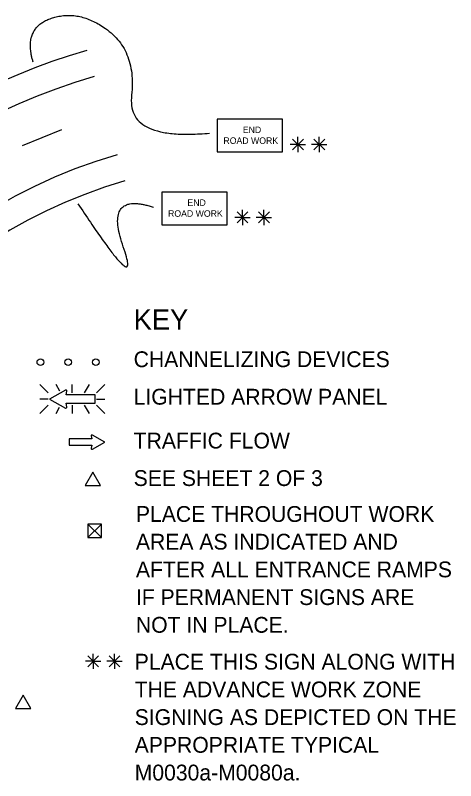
# Model space of a CAD drawing. Extents: x 16563 to 19504, y 6261 to 8279.
# Drawn here: x 17165.8 to 17424.8, y 7689.1 to 8139.2 of the extents above; entities that cross this region are included whole.
import ezdxf

# ---------------------------------------------------------------- set-up
doc = ezdxf.new("R2010")
doc.units = 0
for name, color, linetype in [('ALI_LEGAL_EX', 7, 'Continuous'), ('MT_SCRATCH_LEVEL_E', 7, 'Continuous'), ('PAVT_EDGE_EX', 7, 'Continuous'), ('TRAFFIC_SIGNS_PR', 7, 'Continuous'), ('TYPICAL_TEXT_DIMEN_EX', 7, 'Continuous'), ('TYPICAL_TEXT_DIMEN_PR', 7, 'Continuous')]:
    doc.layers.add(name, color=color, linetype=linetype)

msp = doc.modelspace()

# ---------------------------------------------------------------- linework, layer by layer
at = {"layer": 'ALI_LEGAL_EX'}
msp.add_lwpolyline([(17170.06, 8062.61), (17193.2, 8072.08)], dxfattribs=at)
at = {"layer": 'MT_SCRATCH_LEVEL_E'}
for p, q in [((17210.45, 7891.87), (17210.76, 7890.09)), ((17218.37, 7888.24), (17211.13, 7892.35)), ((17210.76, 7890.09), (17197.5, 7890.09)), ((17197.5, 7890.09), (17197.5, 7886.35)), ((17211.13, 7884.09), (17218.37, 7888.24)), ((17197.5, 7886.35), (17210.76, 7886.35)), ((17210.76, 7886.35), (17210.45, 7884.57))]:
    msp.add_line(p, q, dxfattribs=at)
for centre, start, end in [((17210.9, 7891.94), 60.4248, 189.9638), ((17210.9, 7884.5), 170.0362, 299.7731)]:
    msp.add_arc(centre, 0.463, start, end, dxfattribs=at)
at = {"layer": 'PAVT_EDGE_EX'}
for radius, end in [(380, 157.5011), (364, 165.0045), (316, 180), (300, 180)]:
    msp.add_arc((17314.02, 7753.78), radius, 106.2376, end, dxfattribs=at)
at = {"layer": 'TRAFFIC_SIGNS_PR'}
for p, q in [((17180.22, 7922.05), (17185.15, 7917.11)), ((17191.98, 7918.23), (17189.78, 7922.05)), ((17199.3, 7917.11), (17199.3, 7922.05)), ((17206.54, 7917.11), (17209.39, 7922.05)), ((17213.45, 7917.11), (17218.39, 7922.05)), ((17185.15, 7913.56), (17180.22, 7913.56)), ((17180.22, 7905.07), (17185.15, 7910)), ((17199.3, 7910), (17199.3, 7905.07)), ((17209.43, 7905.07), (17206.58, 7910)), ((17213.45, 7913.56), (17218.39, 7913.56)), ((17213.45, 7910), (17218.39, 7905.07)), ((17189.73, 7905.07), (17191.84, 7908.73))]:
    msp.add_line(p, q, dxfattribs=at)
for points in [[(17284.59, 8058.85), (17323, 8058.85), (17323, 8078.05), (17284.59, 8078.05)], [(17252.02, 8016), (17290.43, 8016), (17290.43, 8035.2), (17252.02, 8035.2)]]:
    msp.add_lwpolyline(points, close=True, dxfattribs=at)
for points in [[(17195.23, 7918.83), (17185.94, 7913.56), (17195.23, 7908.24)], [(17196.11, 7908.87), (17195.7, 7911.13), (17212.72, 7911.13), (17212.72, 7915.94), (17195.7, 7915.94), (17196.11, 7918.22)]]:
    msp.add_lwpolyline(points, dxfattribs=at)
for centre in [(17180.56, 7935.24), (17196.86, 7935.24), (17213.16, 7935.24)]:
    msp.add_circle(centre, 2, dxfattribs=at)
for centre, radius, start, end in [((17195.52, 7918.31), 0.598, 350.7308, 118.8916), ((17195.52, 7908.76), 0.597, 241.4833, 9.9593)]:
    msp.add_arc(centre, radius, start, end, dxfattribs=at)
at = {"layer": 'TYPICAL_TEXT_DIMEN_PR'}
for p, q in [((17332.02, 8063.22), (17332.02, 8067.68)), ((17344.58, 8063.22), (17344.58, 8067.68)), ((17332.02, 8063.22), (17327.49, 8063.22)), ((17328.83, 8066.41), (17335.21, 8060.03)), ((17335.21, 8066.41), (17328.83, 8060.03)), ((17332.02, 8063.22), (17335.21, 8063.22)), ((17332.02, 8063.22), (17336.5, 8063.22)), ((17332.02, 8063.22), (17332.02, 8058.72)), ((17344.58, 8063.22), (17340.04, 8063.22)), ((17341.39, 8066.41), (17347.76, 8060.03)), ((17347.76, 8066.41), (17341.39, 8060.03)), ((17344.58, 8063.22), (17347.76, 8063.22)), ((17344.58, 8063.22), (17349.06, 8063.22)), ((17344.58, 8063.22), (17344.58, 8058.72)), ((17296.26, 8023.56), (17302.64, 8017.18)), ((17302.64, 8023.56), (17296.26, 8017.18)), ((17299.45, 8020.37), (17299.45, 8024.83)), ((17308.82, 8023.56), (17315.2, 8017.18)), ((17315.2, 8023.56), (17308.82, 8017.18)), ((17312.01, 8020.37), (17312.01, 8024.83)), ((17299.45, 8020.37), (17294.92, 8020.37)), ((17299.45, 8020.37), (17302.64, 8020.37)), ((17299.45, 8020.37), (17303.93, 8020.37)), ((17299.45, 8020.37), (17299.45, 8015.87)), ((17312.01, 8020.37), (17307.47, 8020.37)), ((17312.01, 8020.37), (17315.2, 8020.37)), ((17312.01, 8020.37), (17316.49, 8020.37)), ((17312.01, 8020.37), (17312.01, 8015.87)), ((17208.54, 7840.04), (17216.54, 7832.04)), ((17208.54, 7832.04), (17216.54, 7840.04)), ((17208.37, 7762.48), (17214.74, 7756.1)), ((17214.74, 7762.48), (17208.37, 7756.1)), ((17211.56, 7759.29), (17211.56, 7763.75)), ((17220.92, 7762.48), (17227.3, 7756.1)), ((17227.3, 7762.48), (17220.92, 7756.1)), ((17224.11, 7759.29), (17224.11, 7763.75)), ((17211.56, 7759.29), (17207.02, 7759.29)), ((17211.56, 7759.29), (17214.74, 7759.29)), ((17211.56, 7759.29), (17216.03, 7759.29)), ((17211.56, 7759.29), (17211.56, 7754.79)), ((17224.11, 7759.29), (17219.58, 7759.29)), ((17224.11, 7759.29), (17227.3, 7759.29)), ((17224.11, 7759.29), (17228.59, 7759.29)), ((17224.11, 7759.29), (17224.11, 7754.79))]:
    msp.add_line(p, q, dxfattribs=at)
for points in [[(17211.43, 7870.53), (17206.91, 7862.69), (17215.96, 7862.69)], [(17208.54, 7840.04), (17208.54, 7832.04), (17216.54, 7832.04), (17216.54, 7840.04)], [(17170.42, 7739.42), (17165.89, 7731.58), (17174.94, 7731.58)]]:
    msp.add_lwpolyline(points, close=True, dxfattribs=at)
for points in [[(17176.29, 8111.65), (17170.28, 8131.65), (17203.21, 8143.17), (17237.05, 8117.81), (17231.26, 8065.39), (17280.06, 8069.91)], [(17202.65, 8028.44), (17240.88, 7970.26), (17217.67, 8035.97), (17247.02, 8026.39)]]:
    msp.add_open_spline(points, degree=2, dxfattribs=at)

# ---------------------------------------------------------------- texts
at = {"layer": 'TRAFFIC_SIGNS_PR'}
for s, p in [('END', (17299.59, 8069.98)), ('ROAD WORK', (17288.2, 8063.6)), ('END', (17267.03, 8027.13)), ('ROAD WORK', (17255.63, 8020.74))]:
    msp.add_text(s, height=3.832, dxfattribs=at).set_placement(p)
at = {"layer": 'TYPICAL_TEXT_DIMEN_EX'}
for s, height, p in [('KEY', 12, (17235.4, 7954.35)), ('CHANNELIZING DEVICES', 9.3, (17235.4, 7932.3)), ('LIGHTED ARROW PANEL', 9.3, (17235.4, 7910.25)), ('TRAFFIC FLOW', 9.3, (17235.4, 7884.45)), ('SEE SHEET 2 OF 3', 9.3, (17235.4, 7862.4)), ('PLACE THROUGHOUT WORK', 9.3, (17236.72, 7841.29)), ('AREA AS INDICATED AND', 9.3, (17236.72, 7824.99)), ('AFTER ALL ENTRANCE RAMPS', 9.3, (17236.72, 7808.69)), ('IF PERMANENT SIGNS ARE', 9.3, (17236.72, 7792.39)), ('NOT IN PLACE.', 9.3, (17236.72, 7776.09)), ('PLACE THIS SIGN ALONG WITH', 9.3, (17236.01, 7754.41)), ('THE ADVANCE WORK ZONE', 9.3, (17236.01, 7738.11)), ('SIGNING AS DEPICTED ON THE', 9.3, (17236.01, 7721.81)), ('APPROPRIATE TYPICAL', 9.3, (17236.01, 7705.51)), ('M0030a-M0080a.', 9.3, (17236.01, 7689.21))]:
    msp.add_text(s, height=height, dxfattribs=at).set_placement(p)

doc.saveas('drawing.dxf')
